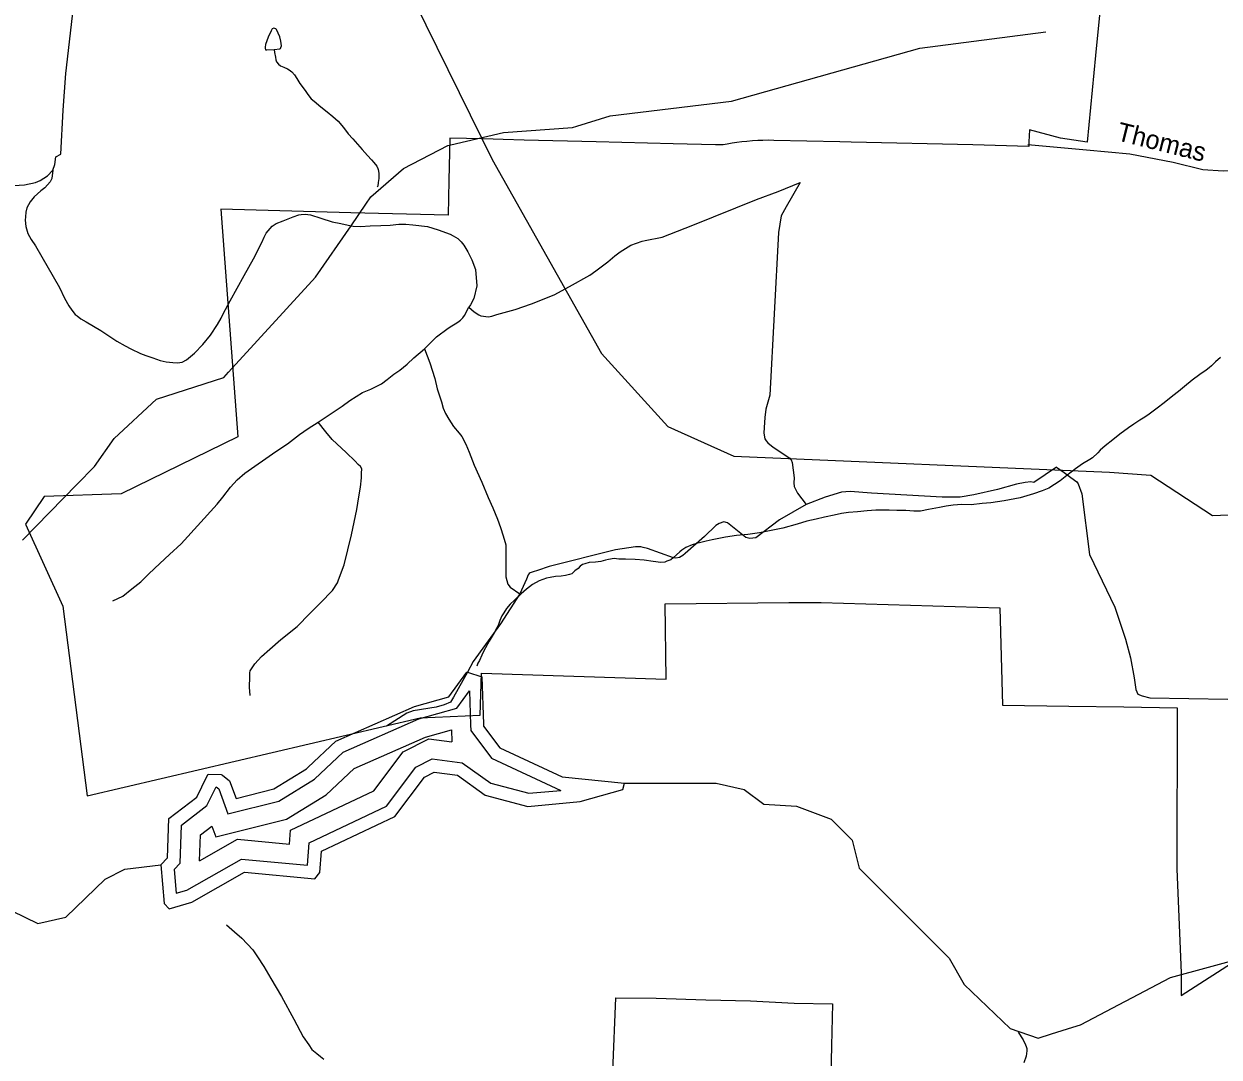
# Model space of a CAD drawing. Extents: x 2001466 to 2224147, y 644118 to 847247.
# Drawn here: x 2037534 to 2043610, y 689045 to 694296 of the extents above; entities that cross this region are included whole.
import ezdxf

# ---------------------------------------------------------------- set-up
doc = ezdxf.new("R2010")
doc.units = 0
for name, color, linetype in [('Exist Boundary Political City Limit New', 7, 'Continuous'), ('Exist Hydrographic Buffer Line', 7, 'Continuous'), ('Exist Hydrographic Creek Single Shore', 7, 'Continuous'), ('Exist Hydrographic Lake Shore', 7, 'Continuous'), ('Exist Hydrographic Misc Water Feature', 7, 'Continuous'), ('Exist Road Non-System Type 51', 7, 'Continuous'), ('Exist Road Non-System Type 51 Label', 7, 'Continuous'), ('Map Preparation Boundary City Limit Buffer Line', 7, 'Continuous'), ('Prop Road Primary Interstate Projected', 7, 'Continuous')]:
    doc.layers.add(name, color=color, linetype=linetype)

msp = doc.modelspace()

# ---------------------------------------------------------------- linework, layer by layer
at = {"layer": 'Exist Boundary Political City Limit New'}
for points in [[(2043042.1, 694750.1), (2042982.2, 694134.6), (2042939.2, 693694.3), (2042803.8, 693714.8), (2042646.6, 693757.4), (2042642.8, 693696.2), (2042641.8, 693673.3), (2042358.1, 693681.1), (2041738.6, 693693.9), (2041681.2, 693696.7), (2041345.8, 693703.8), (2041316.8, 693704.1), (2041290.6, 693703.7), (2041264.2, 693702.7), (2041238.1, 693701.2), (2041209.2, 693698.8), (2041183, 693696.1), (2041158.2, 693692.8), (2041134.5, 693689.3), (2041108.8, 693684.9), (2041087.8, 693680.9), (2041049.8, 693681.7), (2040834.8, 693686.2), (2040442.4, 693696.9), (2040076.8, 693705.4), (2039970.5, 693708.1), (2039868.4, 693710.9), (2039698.2, 693715.2), (2039693.8, 693500), (2039690.1, 693323.1), (2039196.2, 693336.3), (2038534.9, 693354), (2038550.1, 693148.6), (2038584.1, 692694.5), (2038621, 692196.9), (2038027.2, 691907.4), (2037636.2, 691893.8), (2037542.2, 691754.1), (2037730.9, 691337.2), (2037854.6, 690371.9), (2039547.4, 690769.6), (2039852.4, 690782.8), (2039859.2, 690995.7), (2040799.2, 690965.8), (2040794.2, 691347.6), (2041422.1, 691354.4), (2041468.2, 691354.9), (2041480.2, 691354.9), (2041546.1, 691354.8), (2041586, 691354.6), (2042495.8, 691328.9), (2042509.1, 690832.6), (2042845.2, 690828.6), (2043124.8, 690825.5), (2043395.8, 690819.6), (2043395.5, 690000), (2043416.9, 689473), (2043417.1, 689358), (2043536.1, 689433.8), (2043691.1, 689533.4)], [(2040526.8, 688972.8), (2040542.9, 689346.5), (2040748.1, 689344.5), (2041000.5, 689336.3), (2041227.8, 689330.1), (2041449.5, 689319.5), (2041643.6, 689315.2), (2041638.8, 689102.6), (2041635.8, 688948.5)]]:
    msp.add_lwpolyline(points, dxfattribs=at)
at = {"layer": 'Exist Hydrographic Buffer Line'}
for points in [[(2039010.1, 690456.8), (2039156.9, 690595), (2039541.3, 690764.2), (2039733.7, 690818), (2039798.1, 690906.2)], [(2039798.1, 690906.2), (2039804.4, 690733)], [(2039070.2, 690378.2), (2039212, 690511.7), (2039574.6, 690671.3), (2039706.8, 690708.3)], [(2039706.8, 690708.3), (2039709, 690646.4)], [(2039804.4, 690733), (2039805.4, 690704.1), (2039910.5, 690564.6), (2040263.9, 690400.1)], [(2038426.8, 690042.9), (2038618.9, 690152.3), (2038884.3, 690127.4), (2038889.6, 690198.6), (2039313.3, 690398.1), (2039461.8, 690596.6), (2039591.4, 690662), (2039709, 690646.4)], [(2038297.2, 689998.4), (2038308.2, 689877.2), (2038362.4, 689892.9), (2038640.6, 690051.4), (2038975.1, 690020), (2038983.5, 690134), (2039377.4, 690319.5), (2039526.7, 690519.1), (2039608.6, 690560.4), (2039762, 690540.1), (2039907.4, 690436.3), (2040100.7, 690385.4), (2040263.9, 690400.1)], [(2038511.3, 690418.6), (2038524, 690408.4), (2038571.1, 690280.9), (2038829.9, 690346.4), (2039010.1, 690456.8)], [(2038297.2, 689998.4), (2038327.8, 690030.2), (2038335.6, 690224.4), (2038464.2, 690323.6), (2038511.3, 690418.6)], [(2038489.2, 690218.6), (2038509.5, 690163.8), (2038868.6, 690254.7), (2039070.2, 690378.2)], [(2038426.8, 690042.9), (2038432.1, 690174.6), (2038489.2, 690218.6)]]:
    msp.add_lwpolyline(points, dxfattribs=at)
at = {"layer": 'Exist Hydrographic Creek Single Shore'}
msp.add_line((2042757.5, 689162.3), (2042866.1, 689196.4), dxfattribs=at)
for points in [[(2040587.1, 690437), (2041053.2, 690437.3), (2041195.1, 690404.9), (2041295.1, 690330.7), (2041462, 690320.7), (2041637.2, 690254.8), (2041745, 690147.6), (2041779.1, 690005.8), (2042238.2, 689547), (2042313, 689414.2), (2042547, 689189.7), (2042689.1, 689140.9), (2042757.5, 689162.3)], [(2042866.1, 689196.4), (2042905, 689208.6), (2043363.1, 689448.6), (2044504, 689760.1), (2045328.1, 690055.1), (2045714.7, 690286.8)], [(2037215.8, 689780.5), (2037472.1, 689788.3), (2037605.2, 689723.3), (2037747.1, 689756.5), (2037946.2, 689949.3), (2038046.1, 689999.8), (2038229.2, 690022.3)]]:
    msp.add_lwpolyline(points, dxfattribs=at)
at = {"layer": 'Exist Hydrographic Lake Shore'}
msp.add_line((2038970, 690509.3), (2038978.8, 690517.5), dxfattribs=at)
for points in [[(2038978.8, 690517.5), (2039120.1, 690650.5), (2039519.2, 690826.1), (2039694.1, 690875.1), (2039786.2, 691001.2), (2039788, 691000.6)], [(2039788, 691000.6), (2039861.2, 690976.7), (2039869.9, 690736.9)], [(2039869.9, 690736.9), (2039870.2, 690727.1), (2039953.1, 690617.2), (2040270.1, 690469.6), (2040587.1, 690437)], [(2038542.8, 690477.4), (2038579.2, 690448.3), (2038612.2, 690359), (2038804.2, 690407.6), (2038970, 690509.3)], [(2038229.2, 690022.3), (2038247, 689825.1), (2038272, 689798.3), (2038388.1, 689832), (2038655.1, 689984.1), (2039013.1, 689950.5), (2039038.1, 689982.9), (2039046.1, 690091), (2039420.1, 690267.1), (2039570, 690467.5), (2039620.1, 690492.7), (2039737.1, 690477.2), (2039879, 690375.9), (2040095.2, 690319), (2040362.1, 690343.1), (2040578.1, 690404.3), (2040587.1, 690437)], [(2038229.2, 690022.3), (2038263.2, 690057.7), (2038271.2, 690257.7), (2038412.1, 690366.3), (2038463.6, 690470.1)], [(2038463.6, 690470.1), (2038470.1, 690483.3), (2038537.2, 690481.9), (2038542.8, 690477.4)]]:
    msp.add_lwpolyline(points, dxfattribs=at)
at = {"layer": 'Exist Hydrographic Misc Water Feature'}
for p, q in [((2039196.9, 693269.8), (2039272.6, 693379.2)), ((2037526.3, 691672.4), (2037803.4, 691955.3))]:
    msp.add_line(p, q, dxfattribs=at)
for points in [[(2038806.2, 694166.4), (2038834.3, 694168.4), (2038838.2, 694170.4), (2038840.2, 694176.4), (2038842.3, 694184.4), (2038842.1, 694196.4), (2038840, 694208.4), (2038834.1, 694230.4), (2038817.9, 694266.4), (2038814, 694270.4), (2038804, 694274.4), (2038796, 694270.3), (2038790, 694260.3), (2038776.1, 694228.3), (2038762.3, 694190.3), (2038760.3, 694178.2), (2038760.3, 694172.3), (2038762.3, 694164.3), (2038768.3, 694164.3), (2038806.2, 694166.4)], [(2040344, 693775.9), (2040514.3, 693827.7), (2041130.3, 693903.7), (2042088.3, 694173), (2042729.3, 694255)], [(2038806.2, 694166.4), (2038808.3, 694150.4), (2038812.2, 694126.4), (2038814.4, 694112.4), (2038818.3, 694102.4), (2038828.4, 694090.4), (2038838.4, 694082.4), (2038854.4, 694076.5), (2038874.3, 694066.5), (2038882.3, 694062.5), (2038896.4, 694052.6), (2038908.5, 694036.6), (2038920.4, 694018.6), (2038936.4, 693992.6), (2038962.7, 693956.7), (2038976.6, 693936.7), (2038994.7, 693914.8), (2039008.8, 693902.8), (2039042.6, 693874.9), (2039074.8, 693848.9), (2039104.8, 693825), (2039130.8, 693801.1), (2039158.9, 693769.1), (2039182.9, 693737.1), (2039205, 693711.2), (2039229, 693685.3), (2039253, 693657.3), (2039281.1, 693627.4), (2039301.2, 693605.4), (2039313.3, 693591.4), (2039327.2, 693573.4), (2039333.2, 693561.5), (2039335.2, 693555.4), (2039337.3, 693537.4), (2039337.3, 693509.5), (2039335.4, 693489.5), (2039333.7, 693470.9), (2039329.5, 693467.4)], [(2039704.7, 693680.7), (2039972.1, 693743.6), (2040322.2, 693769.3), (2040344, 693775.9)], [(2039272.6, 693379.2), (2039298.1, 693416.1), (2039464.2, 693560.3), (2039689.2, 693677.1), (2039704.7, 693680.7)], [(2038573.8, 692525.3), (2039016.2, 693008.4), (2039196.9, 693269.8)], [(2043616.3, 692599.8), (2043592.3, 692577.7), (2043570.4, 692557.6), (2043558.5, 692547.6), (2043544.3, 692535.6), (2043512.6, 692513.6), (2043472.6, 692485.5), (2043434.6, 692453.4), (2043402.7, 692427.4), (2043374.6, 692405.3), (2043330.7, 692369.3), (2043294.8, 692343.2), (2043254.8, 692313), (2043232.9, 692297), (2043206.8, 692281), (2043177.1, 692261), (2043149, 692242.9), (2043105.1, 692210.8), (2043069.2, 692182.7), (2043031.3, 692150.7), (2043005.3, 692128.7), (2042993.4, 692116.6), (2042965.5, 692090.6), (2042953.4, 692082.6), (2042915.5, 692060.5), (2042879.6, 692034.4), (2042835.5, 692000.4), (2042801.6, 691974.3), (2042773.6, 691954.3), (2042743.6, 691936.2), (2042709.8, 691922.1), (2042665.7, 691908.1), (2042597.8, 691887.9), (2042517.9, 691871.7), (2042450, 691861.6), (2042405.9, 691857.6), (2042349.9, 691851.4), (2042301.9, 691853.4), (2042257.8, 691849.3), (2042222, 691845.2), (2042187.9, 691837.2), (2042131.9, 691827.1), (2042092, 691819), (2042057.9, 691818.9), (2042017.9, 691822.9), (2041972, 691822.7), (2041932, 691824.7), (2041902.1, 691824.6), (2041863.9, 691824.6), (2041820.1, 691820.5), (2041772.1, 691816.4), (2041725.9, 691812.3), (2041690.1, 691808.2), (2041652.1, 691798.2), (2041604.1, 691788.1), (2041562.1, 691778), (2041514.1, 691767.9), (2041464.3, 691753.8), (2041392.3, 691733.7), (2041324.2, 691719.5), (2041272.4, 691709.4), (2041214.3, 691701.3), (2041156.3, 691695.2), (2041100.3, 691687.1), (2041058.5, 691679), (2041032.5, 691673), (2041002.5, 691666.9), (2040974.4, 691660.9), (2040952.5, 691654.8), (2040930.5, 691648.8), (2040898.6, 691634.7), (2040878.5, 691620.7), (2040868.6, 691612.7), (2040850.6, 691596.6), (2040834.6, 691582.6), (2040822.7, 691572.6), (2040802.6, 691564.6), (2040792.8, 691560.5), (2040770.8, 691558.5), (2040732.9, 691564.4), (2040686.7, 691570.3), (2040640.6, 691574.3), (2040592.8, 691576.1), (2040558.8, 691576.1), (2040534.8, 691578.1), (2040504.9, 691574), (2040490.7, 691569.9)], [(2037803.4, 691955.3), (2037893.1, 692047), (2037992.2, 692189.3), (2038208.3, 692388.3), (2038550.1, 692499.5), (2038573.8, 692525.3)], [(2040490.7, 691569.9), (2040466.7, 691563.9), (2040438.8, 691559.9), (2040406.8, 691557.8), (2040384.7, 691551.8), (2040372.8, 691547.7), (2040360.7, 691539.7), (2040350.9, 691527.7), (2040334.9, 691515.7), (2040318.9, 691501.7), (2040307, 691497.7), (2040286.9, 691491.6), (2040264.9, 691489.6), (2040236.9, 691487.5), (2040209, 691481.5), (2040191.1, 691479.4), (2040153, 691465.3), (2040119, 691447.3), (2040089, 691423.3), (2040061.1, 691399.2), (2040027.1, 691367.1), (2040005.4, 691347), (2039987.3, 691325.1), (2039973.4, 691303), (2039963.3, 691287), (2039953.5, 691263), (2039945.5, 691243), (2039937.5, 691226.9), (2039923.5, 691200.9), (2039899.5, 691159), (2039879.7, 691124.9), (2039867.8, 691102.9), (2039861.8, 691086.9), (2039849.7, 691060.8), (2039841.7, 691046.8), (2039836, 691030.8)], [(2042588.8, 689172.4), (2042613, 689132.4), (2042624.9, 689106.4), (2042629, 689098.4), (2042632.9, 689088.4), (2042632.9, 689076.4), (2042629, 689050.4), (2042617.1, 689016.4)]]:
    msp.add_lwpolyline(points, dxfattribs=at)
at = {"layer": 'Exist Road Non-System Type 51'}
for points in [[(2037680, 693552.5), (2037690.6, 693580.3), (2037695.4, 693620.2), (2037720.8, 693633.3), (2037733.6, 693857.3), (2037746.4, 694042.8), (2037791.2, 694426.7)], [(2044429.1, 693805.1), (2044357.3, 693784), (2044218, 693731.2), (2044042.7, 693644.6), (2043875.9, 693585.4), (2043749.3, 693551.6), (2043631, 693547.4), (2043527.6, 693553.7), (2043375.6, 693591.7), (2043156, 693632.9), (2042935.4, 693654.1), (2042637.7, 693680.5)], [(2037428.4, 693471.7), (2037536.5, 693477.5), (2037592.7, 693490.3), (2037616.9, 693499.8), (2037635.2, 693511.5), (2037653.4, 693523.1), (2037680, 693552.5)], [(2037680, 693552.5), (2037675.2, 693510.6), (2037666.8, 693492.8), (2037640.2, 693463.4), (2037619.9, 693447.8), (2037585.2, 693416.5), (2037564.7, 693390.9), (2037548.1, 693361.2), (2037543.7, 693339.3), (2037541.2, 693315.4), (2037540.8, 693297.4), (2037544.1, 693265.3), (2037553.5, 693231.1), (2037570.8, 693200.8), (2037592.2, 693168.3), (2037713.8, 692955.8), (2037740.7, 692901.3), (2037761.9, 692862.9), (2037777.5, 692840.5), (2037795, 692818.2), (2037804.9, 692812), (2037822.6, 692797.6), (2037850.3, 692781.1), (2037925.4, 692737.5), (2038006.3, 692683.9), (2038047.8, 692659), (2038077.5, 692644.4), (2038127, 692621.4), (2038152.8, 692610.9), (2038188.5, 692598.2), (2038226.3, 692585.4), (2038256.1, 692578.8), (2038290, 692574.1), (2038314, 692573.6), (2038338.1, 692577.1), (2038360.3, 692588.7), (2038401, 692621.8), (2038443.9, 692667), (2038482.9, 692714.2), (2038518, 692767.4), (2038535.6, 692801)], [(2039795.8, 692855.4), (2039823.4, 692832.9), (2039847, 692816.4), (2039856.9, 692812.2), (2039894.8, 692807.4), (2039912.9, 692811), (2039937.1, 692818.5), (2040031.6, 692844.6), (2040114.2, 692872.9), (2040229.1, 692918.6), (2040308, 692961), (2040411.2, 693018.9), (2040441.6, 693040.3), (2040502.6, 693087), (2040537.2, 693116.3), (2040565.6, 693137.7), (2040618.3, 693170.7), (2040648.5, 693182), (2040676.7, 693191.5), (2040692.8, 693195.1), (2040777.6, 693212.3), (2040934.1, 693272.1), (2041258.3, 693403.1), (2041367.6, 693443.8), (2041480.2, 693488.9)], [(2041480.2, 693488.9), (2041408, 693366.4), (2041383.5, 693321), (2041370.2, 693235.9), (2041326, 692408.3), (2041305.4, 692337.4), (2041299.6, 692294.6), (2041296.7, 692244), (2041295.7, 692215.5), (2041300.3, 692187.1), (2041306.6, 692177.5), (2041316.2, 692167.3), (2041343.1, 692144.9), (2041427.9, 692089), (2041433.9, 692080.4), (2041439.4, 692066.2), (2041449.6, 691989.1), (2041448.1, 691963.3), (2041450, 691945.5), (2041455.7, 691930.9), (2041466.8, 691911.5), (2041509.8, 691854)], [(2038535.6, 692801), (2038547.1, 692822.9), (2038582.5, 692888.1), (2038617.8, 692953.4), (2038653.1, 693016.7), (2038700.8, 693101.7), (2038742.5, 693184.9), (2038755.1, 693212.6), (2038765.5, 693232.4), (2038796.2, 693267.8), (2038816.5, 693281.4), (2038850.8, 693294.7), (2038903.2, 693315.6), (2038931.4, 693325), (2038943.4, 693326.8), (2038963.5, 693328.4), (2038991.4, 693325.8), (2039043.1, 693308.8), (2039100.7, 693289.6), (2039144.5, 693280.7), (2039196.9, 693269.8)], [(2039196.9, 693269.8), (2039208.2, 693267.4), (2039244.2, 693266.7), (2039294.3, 693269.6), (2039348.3, 693270.5), (2039396.3, 693273.6), (2039440.5, 693278.7), (2039474.4, 693278), (2039510.4, 693275.2), (2039586.2, 693265.7), (2039639.8, 693248.6), (2039701.4, 693227.3), (2039715.2, 693219.1), (2039738.9, 693204.6), (2039756.6, 693188.2), (2039770.3, 693171.9), (2039789.6, 693137.5), (2039810.7, 693097.1), (2039829.7, 693046.7), (2039836, 692964.6), (2039820.7, 692900.9), (2039804.1, 692867.2), (2039795.8, 692855.4)], [(2039569.5, 692644), (2039630.7, 692704.8), (2039689.7, 692749.6), (2039709.9, 692761.2), (2039726.1, 692770.8), (2039740.3, 692780.5), (2039752.5, 692790.3), (2039764.7, 692802), (2039773, 692813.9), (2039795.8, 692855.4)], [(2039029.9, 692271), (2039151.5, 692352.5), (2039190.1, 692381.7), (2039255, 692422.4), (2039297.3, 692439.6), (2039351.9, 692466.5), (2039380.3, 692487.9), (2039414.9, 692515.2), (2039445.3, 692536.5), (2039481.9, 692565.8), (2039516.6, 692599.1), (2039569.5, 692644)], [(2039569.5, 692644), (2039598.1, 692573.4), (2039622.4, 692492.9), (2039635.3, 692440.7), (2039656, 692374.3), (2039665.3, 692342.1), (2039676.8, 692315.8), (2039694.2, 692287.5), (2039717.4, 692249), (2039746.8, 692216.4), (2039760.4, 692198.1), (2039779.6, 692159.7), (2039796.8, 692119.4), (2039823.4, 692052.8), (2039861.7, 691966.1), (2039894.1, 691889.4), (2039917, 691836.9), (2039941.8, 691778.4), (2039957, 691736.1), (2039970.1, 691693.8), (2039983.1, 691647.6), (2039983.7, 691485), (2039993, 691447.8), (2040005.4, 691433.9), (2040054, 691399.5)], [(2037985.3, 691364.3), (2038035.8, 691387.2), (2038082.6, 691424.3), (2038127.3, 691459.4), (2038168.1, 691500.5), (2038225.2, 691553.4), (2038274.1, 691598.4), (2038333.2, 691653.2), (2038515.4, 691855.5), (2038544.1, 691890.9), (2038583.1, 691942.1), (2038617.9, 691979.4), (2038656.6, 692012.6), (2038814.8, 692123.4), (2038873.6, 692162.2), (2038934.6, 692208.9), (2038979.2, 692240), (2039029.9, 692271)], [(2038683.5, 690882), (2038680.4, 690924.1), (2038681.5, 690978.1), (2038681.7, 690990.1), (2038681.9, 690998.1), (2038684.1, 691008), (2038694.4, 691023.8), (2038706.8, 691043.6), (2038741.6, 691080.9), (2038784.3, 691118), (2038839.3, 691166.9), (2038922.7, 691233.2), (2038988, 691299.8), (2039041.1, 691352.8), (2039102.4, 691415.5), (2039127.2, 691455), (2039133.5, 691470.9), (2039161.1, 691546.3), (2039198.2, 691699.6), (2039226.8, 691827), (2039236.1, 691892.8), (2039245.1, 691940.6), (2039250.1, 691988.5), (2039250.6, 692012.5), (2039251, 692034.5), (2039245.3, 692046.6), (2039233.5, 692056.9), (2039217.8, 692073.2), (2039172.7, 692118.1), (2039100.1, 692183.6), (2039068.9, 692222.2), (2039029.9, 692271)], [(2042782.8, 692043.4), (2042668.3, 691964.9), (2042653.1, 691968.2), (2042623.6, 691965.1), (2042579.7, 691956.2), (2042484, 691930.1), (2042362.9, 691902.7), (2042293, 691891.3), (2042245.9, 691890), (2042202.7, 691891.3), (2042112.4, 691896.3), (2041843.4, 691911.6), (2041733.5, 691919.2), (2041690.1, 691915.8), (2041607.6, 691890.2), (2041509.8, 691854)], [(2042782.8, 692043.4), (2042822, 692015.9), (2042856.7, 691990.5), (2042885.7, 691968.7), (2042893.6, 691957.6), (2042912.1, 691906.9), (2042950.4, 691598.5)], [(2041509.8, 691854), (2041374.5, 691774.5), (2041253.8, 691683.2), (2041224.4, 691680.1), (2041204.3, 691686.3), (2041109.8, 691760.6), (2041091.2, 691765.3), (2041068, 691757.5), (2041050.6, 691745.9), (2040993.1, 691690.4), (2040894.6, 691604.3), (2040883.5, 691593.8), (2040866.3, 691584.3), (2040847.9, 691581.1), (2040835.4, 691582.3), (2040703.6, 691629), (2040682.6, 691634), (2040669.3, 691637.4), (2040642.8, 691638.3), (2040541.1, 691623.4), (2040203.2, 691537.6), (2040145.1, 691518.5), (2040122.2, 691511), (2040107.7, 691505.8), (2040102.5, 691502.7), (2040096.6, 691495.9), (2040087.9, 691474.1), (2040054, 691399.5)], [(2042950.4, 691598.5), (2043080.1, 691331.7), (2043134, 691168.3), (2043159.4, 691074.3), (2043177.5, 690972.3), (2043186.7, 690913.8), (2043196.8, 690889.4), (2043217.9, 690880.7), (2043257.9, 690870.7), (2044050.8, 690856.4), (2044105.5, 690862.1), (2044147.1, 690857.9), (2044175.5, 690856.9), (2044187.1, 690849.7), (2044194.8, 690844.3), (2044206.5, 690831.4), (2044207.7, 690819.4)], [(2040054, 691399.5), (2039956.3, 691246.1), (2039818.1, 691055.2), (2039788, 691000.6)], [(2039788, 691000.6), (2039717.9, 690873.8), (2039703, 690848), (2039670.8, 690835.7), (2039628.9, 690822.9), (2039513.2, 690805.3), (2039480.1, 690792.4), (2039377.4, 690726.6)], [(2038563.7, 689716.4), (2038605, 689681.6), (2038642.3, 689648.8), (2038697.1, 689589.7), (2038720.4, 689555.2), (2038753.4, 689504.6), (2038788.1, 689443.9), (2038842.3, 689352.8), (2038905.9, 689237.5), (2038954.1, 689148.5), (2038981.3, 689107.9), (2038996.8, 689083.6), (2039022.4, 689063.1), (2039042.1, 689048.7), (2039057.8, 689034.4)]]:
    msp.add_lwpolyline(points, dxfattribs=at)
at = {"layer": 'Map Preparation Boundary City Limit Buffer Line'}
for points in [[(2043042.1, 694750.1), (2042982.2, 694134.6), (2042939.2, 693694.3), (2042803.8, 693714.8), (2042646.6, 693757.4), (2042642.8, 693696.2), (2042641.8, 693673.3), (2042358.1, 693681.1), (2041738.6, 693693.9), (2041681.2, 693696.7), (2041345.8, 693703.8), (2041316.8, 693704.1), (2041290.6, 693703.7), (2041264.2, 693702.7), (2041238.1, 693701.2), (2041209.2, 693698.8), (2041183, 693696.1), (2041158.2, 693692.8), (2041134.5, 693689.3), (2041108.8, 693684.9), (2041087.8, 693680.9), (2041049.8, 693681.7), (2040834.8, 693686.2), (2040442.4, 693696.9), (2040076.8, 693705.4), (2039970.5, 693708.1), (2039868.4, 693710.9), (2039698.2, 693715.2), (2039693.8, 693500), (2039690.1, 693323.1), (2039196.2, 693336.3), (2038534.9, 693354), (2038550.1, 693148.6), (2038584.1, 692694.5), (2038621, 692196.9), (2038027.2, 691907.4), (2037636.2, 691893.8), (2037542.2, 691754.1), (2037730.9, 691337.2), (2037854.6, 690371.9), (2039547.4, 690769.6), (2039852.4, 690782.8), (2039859.2, 690995.7), (2040799.2, 690965.8), (2040794.2, 691347.6), (2041422.1, 691354.4), (2041468.2, 691354.9), (2041480.2, 691354.9), (2041546.1, 691354.8), (2041586, 691354.6), (2042495.8, 691328.9), (2042509.1, 690832.6), (2042845.2, 690828.6), (2043124.8, 690825.5), (2043395.8, 690819.6), (2043395.5, 690000), (2043416.9, 689473), (2043417.1, 689358), (2043536.1, 689433.8), (2043691.1, 689533.4)], [(2040526.8, 688972.8), (2040542.9, 689346.5), (2040748.1, 689344.5), (2041000.5, 689336.3), (2041227.8, 689330.1), (2041449.5, 689319.5), (2041643.6, 689315.2), (2041638.8, 689102.6), (2041635.8, 688948.5)]]:
    msp.add_lwpolyline(points, dxfattribs=at)
at = {"layer": 'Prop Road Primary Interstate Projected'}
msp.add_lwpolyline([(2039184.3, 695090.2), (2039914.3, 693606.2), (2040470.6, 692620.7), (2040806.6, 692249.7), (2041142.7, 692099), (2043052.5, 692017.2), (2043262.9, 692002.1), (2043576.2, 691797.5), (2043865.9, 691809.1), (2044120.9, 692006.2), (2044642.3, 692029.4), (2044897.3, 692029.4), (2045279.7, 692041)], dxfattribs=at)

# ---------------------------------------------------------------- texts
at = {"layer": 'Exist Road Non-System Type 51 Label'}
msp.add_text('Thomas', height=95, rotation=345.99436, dxfattribs=at).set_placement((2043084.1, 693705.6))

doc.saveas('drawing.dxf')
